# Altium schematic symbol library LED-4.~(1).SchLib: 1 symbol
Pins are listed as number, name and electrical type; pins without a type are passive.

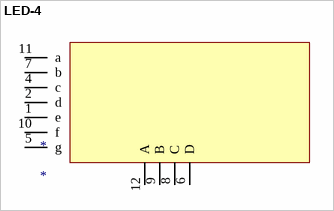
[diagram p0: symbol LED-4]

## LED-4
designator *
pins: 1 e, 2 d, 4 c, 5 g, 6 D, 7 b, 8 C, 9 B, 10 f, 11 a, 12 A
